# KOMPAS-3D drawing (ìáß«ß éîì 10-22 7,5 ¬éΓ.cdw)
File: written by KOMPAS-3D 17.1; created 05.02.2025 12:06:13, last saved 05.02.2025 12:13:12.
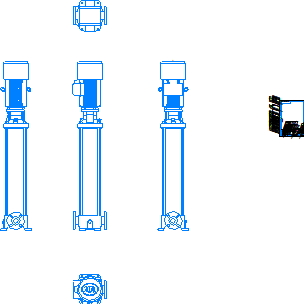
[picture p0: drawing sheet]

Sheet 1: A4, portrait

Title block, sheet 1: name: Насос ВМН 10-22 / 7,5 кВт; designation: Насос ВМН 10-22 7,5 кВт; material: Сталь 10  ГОСТ 1050-2013; mass: 277,77; sheets: 1; sheet format: A4; stored path: \\adlc.lan\data\АДЛ_ПКД\3D-модели\ADL production\Насосы ГРАНПАМП\Насосы ВМН\ВМН10\KOMPAS 3D\Насос ВМН 10-22 7,5 кВт.cdw

Views: Проекционный вид 2, Проекционный вид 3, Проекционный вид 4, Проекционный вид 5
Referenced files in \\adlc.lan\data\АДЛ_ПКД\3D-модели\ADL production\Насосы ГРАНПАМП\Насосы ВМН\ВМН10\KOMPAS 3D\: Насос ВМН 10-22 7,5 кВт.m3d
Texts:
  Andrey
  АДЛ
Dimensions and other numbers on the sheet: 1:1; 1; 7,5 кВт; 277,77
